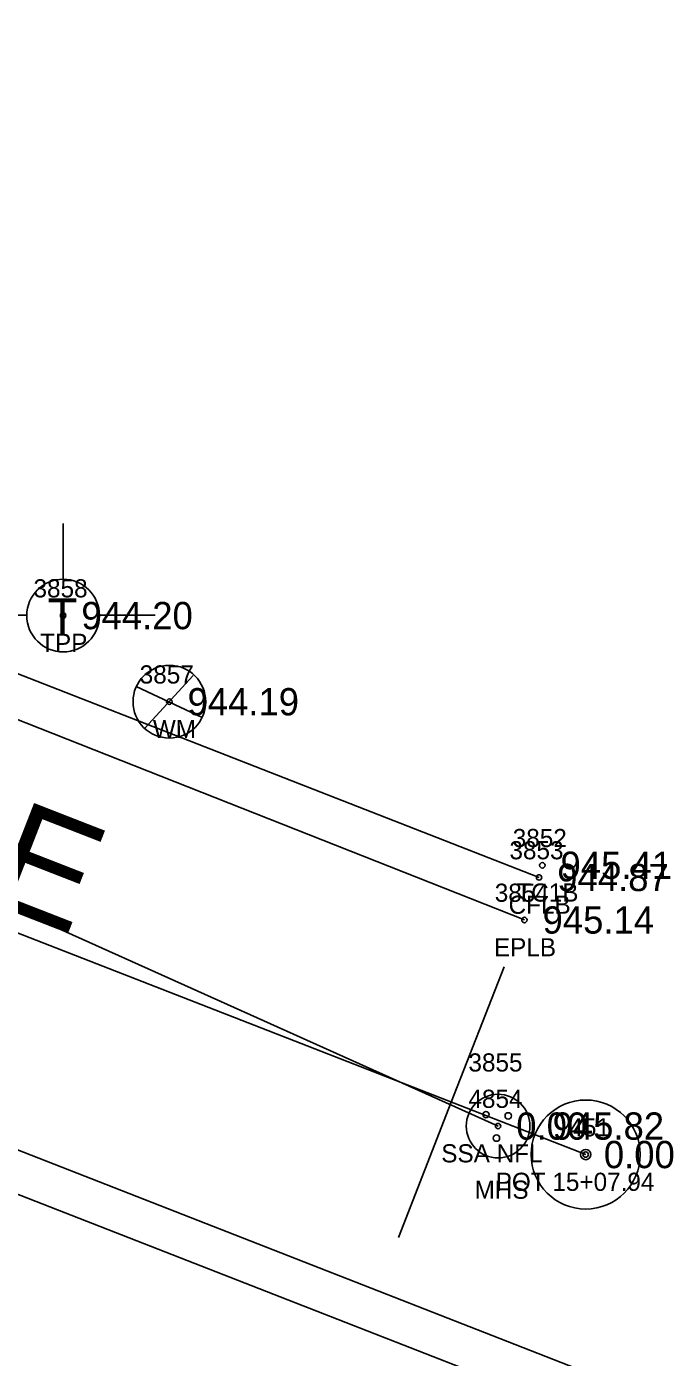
# Model space of a CAD drawing. Extents: x 1575382 to 1578175, y 1099175 to 1101955.
# Drawn here: x 1577623.1 to 1577658.7, y 1100791.3 to 1100864.5 of the extents above; entities that cross this region are included whole.
import ezdxf

# ---------------------------------------------------------------- set-up
doc = ezdxf.new("R2010")
doc.units = 0
for name, color, linetype in [('RD_EX_Conc', 7, 'Continuous'), ('RD_EX_Conc_txCode', 7, 'Continuous'), ('RD_EX_DR_Inlet', 7, 'Continuous'), ('RD_EX_Road', 7, 'Continuous'), ('RD_EX_Road_txCode', 7, 'Continuous'), ('RD_EX_TX_Conc_ELEV', 7, 'Continuous'), ('RD_EX_TX_Road_ELEV', 7, 'Continuous'), ('RD_EX_TX_UT_ELEV', 7, 'Continuous'), ('RD_EX_UT', 7, 'Continuous'), ('RD_EX_UT_txCode', 7, 'Continuous'), ('RD_HC_Cl', 7, 'Continuous'), ('RD_HC_Data', 7, 'Continuous'), ('RD_HC_Data_Tic', 7, 'Continuous'), ('RD_HC_Survey_ELEV', 7, 'Continuous'), ('RD_HC_txCode', 7, 'Continuous'), ('RD_SMD_Locator', 7, 'Continuous')]:
    doc.layers.add(name, color=color, linetype=linetype)

msp = doc.modelspace()

# ---------------------------------------------------------------- linework, layer by layer
at = {"layer": 'RD_EX_Conc'}
for points in [[(1577395.736, 1100920.66), (1577401.57, 1100919.247), (1577405.995, 1100916.997), (1577418.291, 1100908.164), (1577459.556, 1100878.434), (1577501.424, 1100850.964), (1577548.664, 1100829.067), (1577593.786, 1100811.493), (1577656.516, 1100786.999)], [(1577521.961, 1100892.215), (1577519.026, 1100884.741), (1577517.864, 1100878.699), (1577519.281, 1100873.69), (1577525.338, 1100868.314), (1577559.486, 1100853.531), (1577604.815, 1100835.833), (1577651.288, 1100817.68)]]:
    msp.add_lwpolyline(points, dxfattribs=at)
at = {"layer": 'RD_EX_DR_Inlet'}
for centre, radius in [((1577649.032, 1100804.001), 1.75), ((1577648.367, 1100804.631), 0.175), ((1577649.591, 1100804.561), 0.175), ((1577648.944, 1100803.337), 0.175)]:
    msp.add_circle(centre, radius, dxfattribs=at)
at = {"layer": 'RD_EX_Road'}
for points in [[(1577532.834, 1100925.692), (1577520.073, 1100893.352), (1577517.119, 1100885.443), (1577515.828, 1100878.695), (1577517.186, 1100872.6), (1577524.619, 1100866.376), (1577558.241, 1100851.545), (1577603.805, 1100833.782), (1577650.481, 1100815.34)], [(1577549.626, 1100831.199), (1577595.43, 1100813.305), (1577657.483, 1100789.049)]]:
    msp.add_lwpolyline(points, dxfattribs=at)
at = {"layer": 'RD_EX_UT'}
for p, q in [((1577625.1, 1100837.16), (1577625.1, 1100834.09)), ((1577620.17, 1100832.105), (1577623.1, 1100832.105)), ((1577627.1, 1100832.105), (1577630.17, 1100832.105)), ((1577629.592, 1100825.893), (1577632.259, 1100828.789)), ((1577629.11, 1100828.188), (1577632.741, 1100826.475))]:
    msp.add_line(p, q, dxfattribs=at)
msp.add_lwpolyline([(1577649.032, 1100804.001), (1577493.924, 1100873.726), (1577386.899, 1100948.146)], dxfattribs=at)
for centre in [(1577625.1, 1100832.09), (1577630.944, 1100827.351)]:
    msp.add_circle(centre, 2, dxfattribs=at)
at = {"layer": 'RD_HC_Cl'}
msp.add_line((1577551.724, 1100842.238), (1577653.853, 1100802.434), dxfattribs=at)
at = {"layer": 'RD_HC_Data'}
for radius in [3, 0.282]:
    msp.add_circle((1577653.853, 1100802.434), radius, dxfattribs=at)
at = {"layer": 'RD_HC_Data_Tic'}
for q in [(1577649.365, 1100812.769), (1577643.554, 1100797.862)]:
    msp.add_line((1577646.46, 1100805.316), q, dxfattribs=at)
at = {"layer": 'RD_SMD_Locator'}
for centre, radius in [((1577625.1, 1100832.09), 0.15), ((1577630.944, 1100827.351), 0.15), ((1577651.47, 1100818.351), 0.15), ((1577651.288, 1100817.68), 0.15), ((1577650.481, 1100815.34), 0.15), ((1577649.032, 1100804.001), 0.15), ((1577649.032, 1100804.001), 0.001), ((1577653.853, 1100802.434), 0.15)]:
    msp.add_circle(centre, radius, dxfattribs=at)

# ---------------------------------------------------------------- texts
at = {"layer": 'RD_EX_Conc_txCode'}
for s, p in [('3852', (1577649.84, 1100819.351)), ('3853', (1577649.658, 1100818.68)), ('TC1B', (1577650.037, 1100816.351)), ('CFLB', (1577649.611, 1100815.68))]:
    msp.add_text(s, height=1, dxfattribs=at).set_placement(p)
at = {"layer": 'RD_EX_Road_txCode'}
for s, p in [('3854', (1577648.851, 1100816.34)), ('EPLB', (1577648.804, 1100813.34))]:
    msp.add_text(s, height=1, dxfattribs=at).set_placement(p)
at = {"layer": 'RD_EX_TX_Conc_ELEV'}
for s, p in [('945.41', (1577652.47, 1100817.601)), ('944.87', (1577652.288, 1100816.93))]:
    msp.add_text(s, height=1.5, dxfattribs=at).set_placement(p)
at = {"layer": 'RD_EX_TX_Road_ELEV'}
msp.add_text('945.14', height=1.5, dxfattribs=at).set_placement((1577651.481, 1100814.59))
at = {"layer": 'RD_EX_TX_UT_ELEV'}
for s, p in [('944.20', (1577626.1, 1100831.34)), ('944.19', (1577631.944, 1100826.601)), ('0.00', (1577650.032, 1100803.251)), ('945.82', (1577652.032, 1100803.251))]:
    msp.add_text(s, height=1.5, dxfattribs=at).set_placement(p)
at = {"layer": 'RD_EX_UT'}
msp.add_text('T', height=2, dxfattribs=at).set_placement((1577624.251, 1100831.043))
at = {"layer": 'RD_EX_UT_txCode'}
for s, p in [('3858', (1577623.47, 1100833.09)), ('TPP', (1577623.833, 1100830.09)), ('3857', (1577629.314, 1100828.351)), ('WM', (1577630.038, 1100825.351)), ('3855', (1577647.402, 1100807.001)), ('4854', (1577647.402, 1100805.001)), ('SSA NFL', (1577645.906, 1100802.001)), ('MHS', (1577647.74, 1100800.001))]:
    msp.add_text(s, height=1, dxfattribs=at).set_placement(p)
at = {"layer": 'RD_HC_Data'}
msp.add_text('S 68%%d 42\' 25" E', height=6, rotation=338.70698, dxfattribs=at).set_placement((1577575.398, 1100834.085))
at = {"layer": 'RD_HC_Survey_ELEV'}
msp.add_text('0.00', height=1.5, dxfattribs=at).set_placement((1577654.853, 1100801.684))
at = {"layer": 'RD_HC_txCode'}
for s, p in [('451', (1577652.956, 1100803.434)), ('POT 15+07.94', (1577648.9, 1100800.434))]:
    msp.add_text(s, height=1, dxfattribs=at).set_placement(p)

doc.saveas('drawing.dxf')
